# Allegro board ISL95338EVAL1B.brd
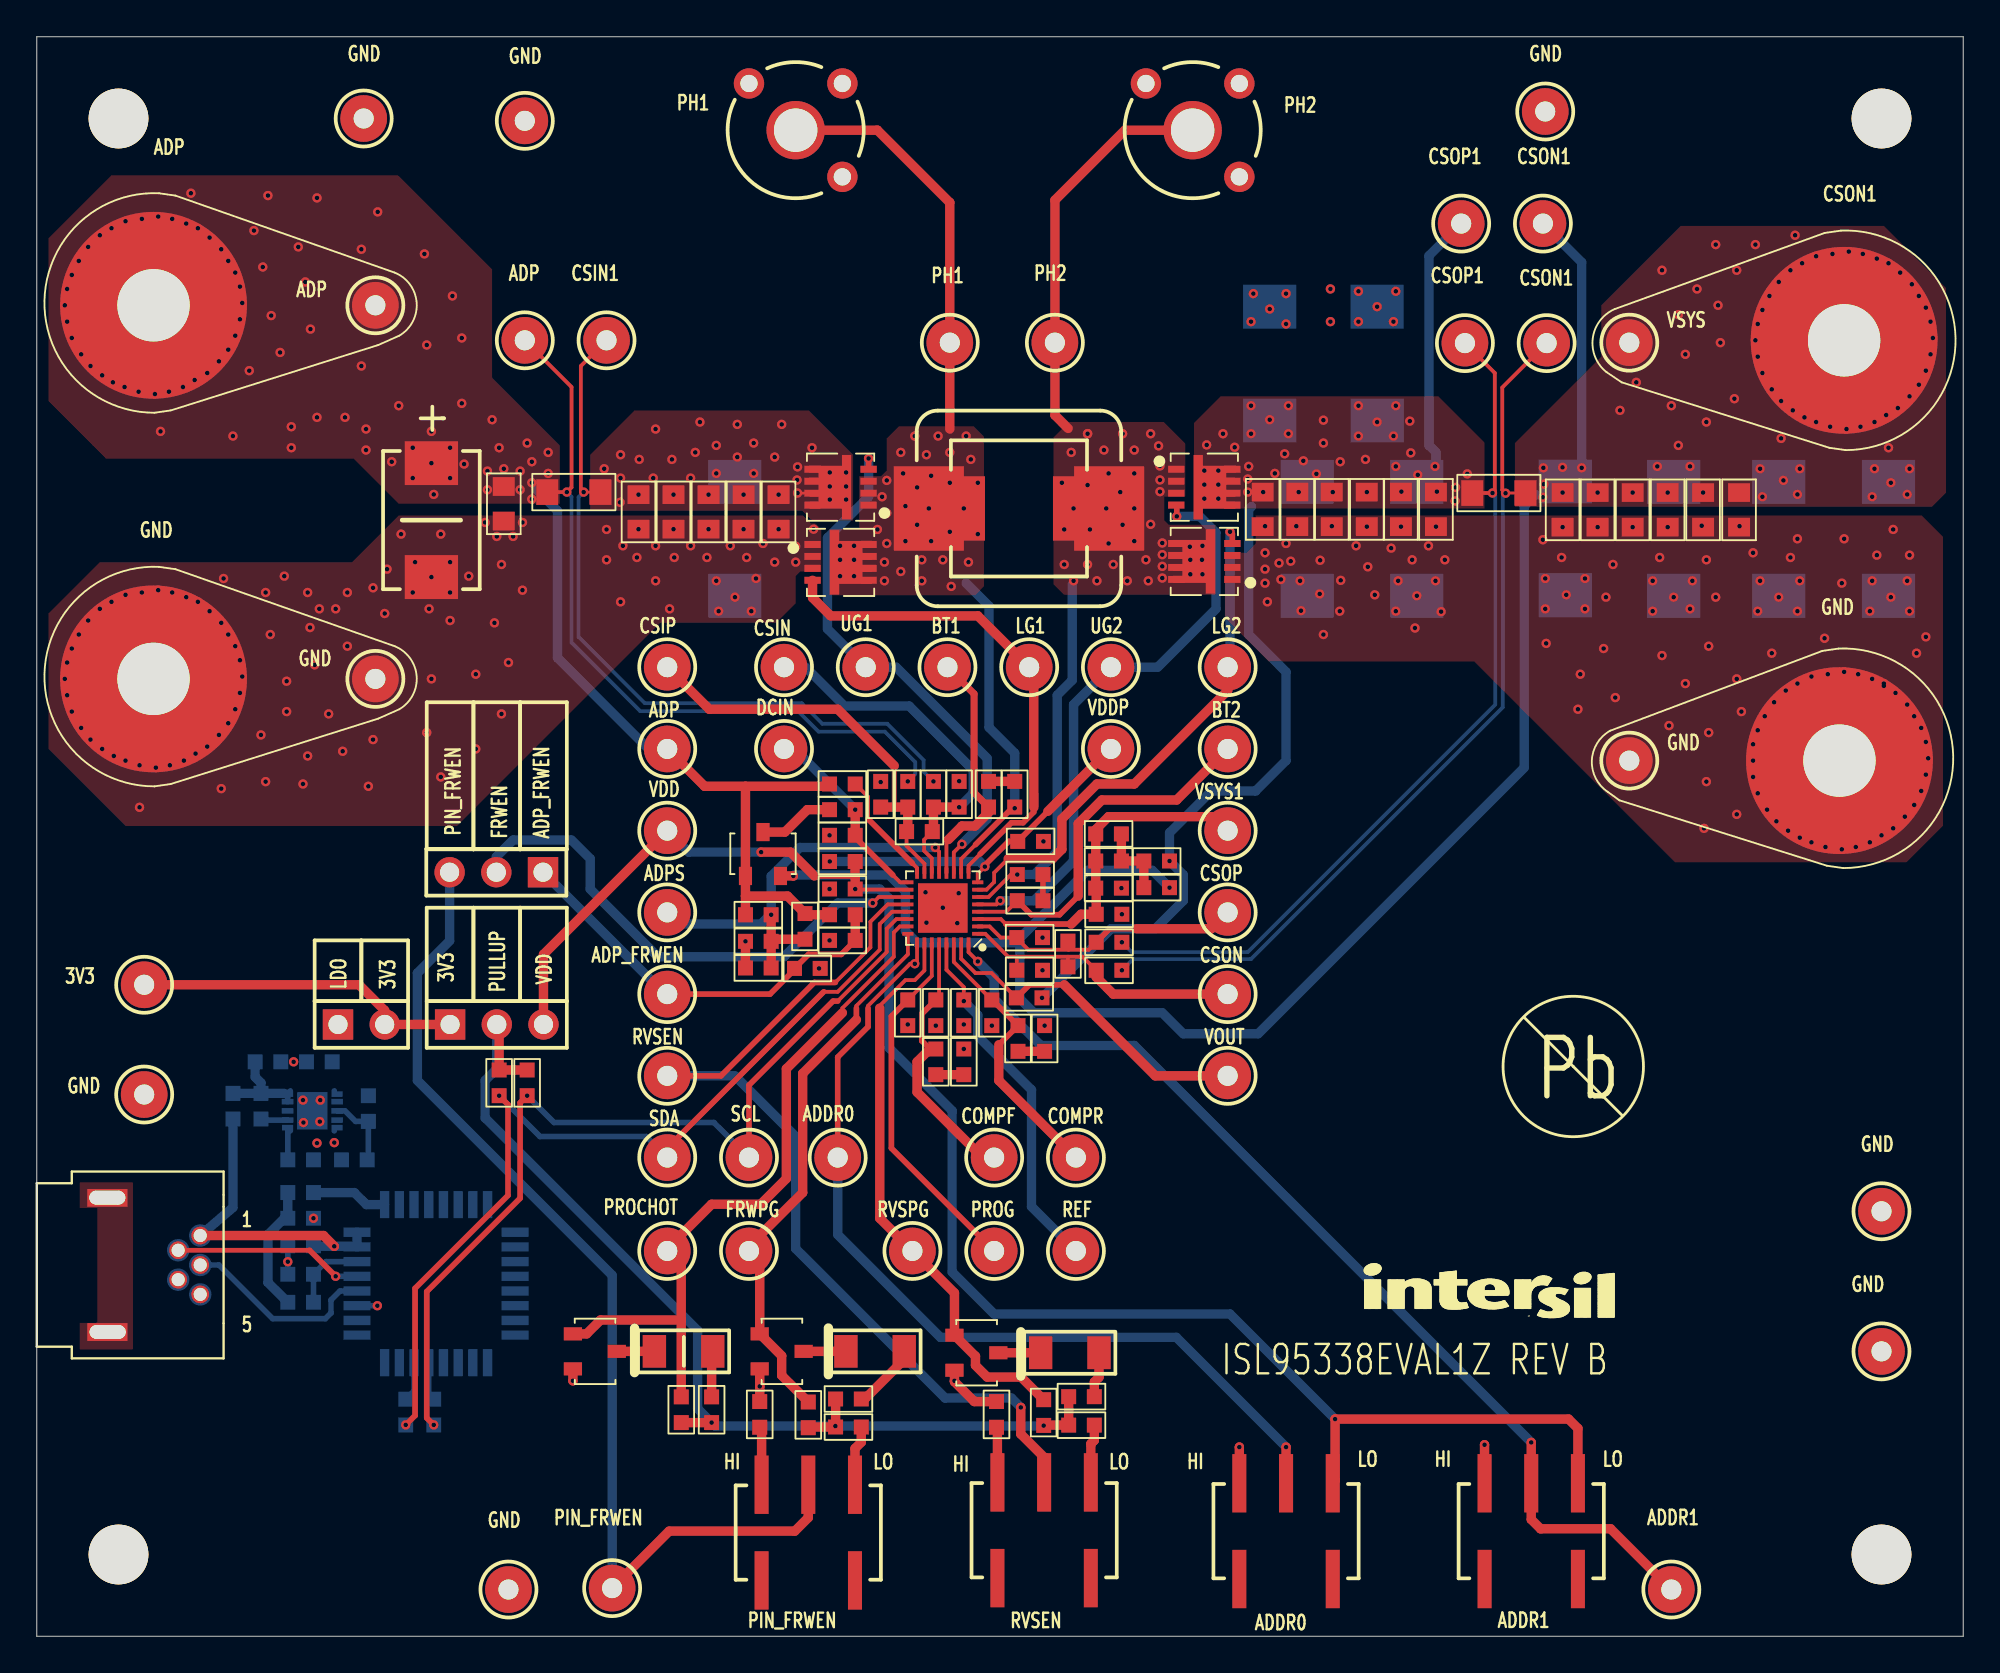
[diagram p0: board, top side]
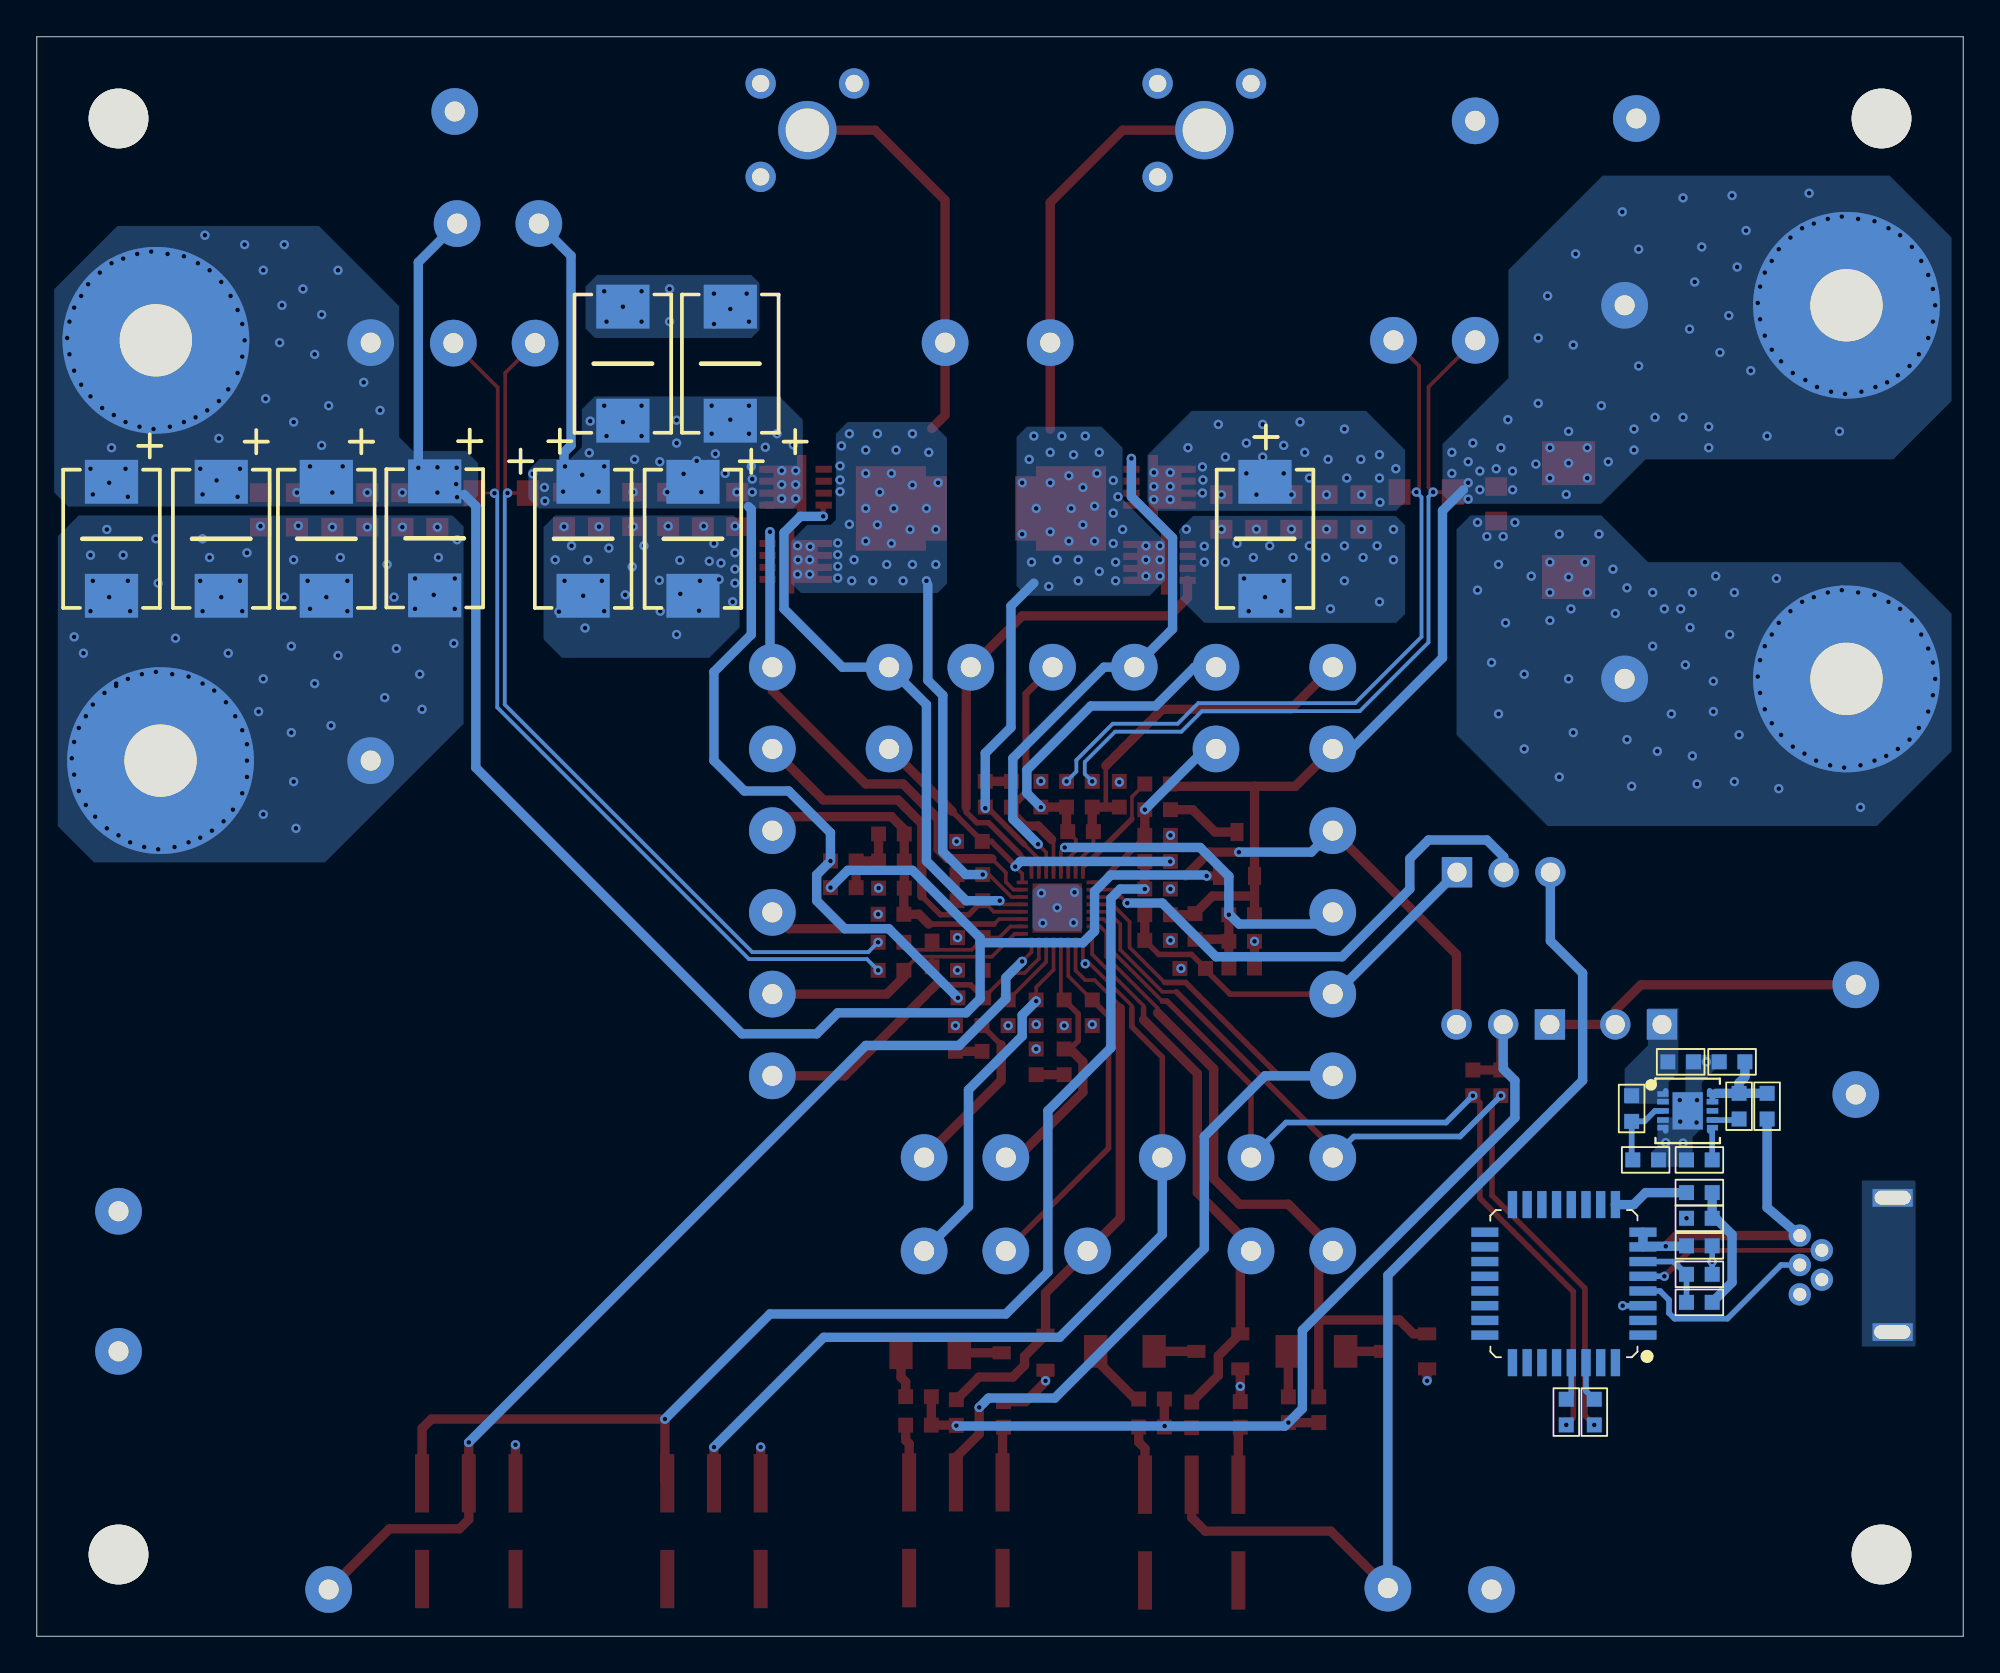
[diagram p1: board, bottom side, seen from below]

Outline 104.78 x 87 mm; copper layers: TOP, L2, L3, BOTTOM. Coordinates in mm from the lower left corner of the outline.
Outline path: 0,87 0,0 104.78,0 104.78,87 0,87 ; 3.18,23.5 arc(2.87,23.87) 3.21,24.21 4.47,24.21 arc(4.8,23.82) 4.39,23.5 3.18,23.5 ; 3.21,16.2 arc(2.9,16.56) 3.23,16.91 4.49,16.91 arc(4.82,16.51) 4.42,16.2 3.21,16.2

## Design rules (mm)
nets with their own width: min track width 0.152; nets CSON1 DCIN

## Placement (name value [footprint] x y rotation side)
C1  NC  [CAP_SANYO_D2]  100.71 59.69 270 bottom
C2  NC  [CAP_SANYO_D2]  94.74 59.69 270 bottom
C3  NC  [CAP_SANYO_D2]  89.03 59.69 270 bottom
C4  NC  [CAP_SANYO_D2]  83.13 59.72 270 bottom
C5  NC  [SM0805_DELTA]  90.63 61.26 90 top
C6  NC  [SM0805_DELTA]  92.58 61.26 90 top
C7  NC  [SM0805_DELTA]  82.99 61.26 90 top
C8  NC  [SM0805_DELTA]  84.89 61.26 90 top
C9  NC  [SM0805_DELTA]  86.8 61.26 90 top
C10  NC  [SM0805_DELTA]  88.7 61.26 90 top
C18  NC  [SM0805_DELTA]  25.4 61.59 90 top
C19  47u  [CAP_SANYO_D2]  37.97 59.69 270 bottom
C20  22u  [SM0805_DELTA]  40.35 61.15 90 top
C21  22u  [SM0805_DELTA]  38.44 61.15 90 top
C22  22u  [SM0805_DELTA]  36.54 61.15 90 top
C23  22u  [SM0805_DELTA]  34.63 61.15 90 top
C24  22u  [SM0805_DELTA]  32.73 61.15 90 top
C26  4.7uF  [SM0603_DELTA]  48.01 43.76 180 top
C28  1u  [SM0603_DELTA]  45.9 45.8 270 top
C29  1u  [SM0603_DELTA]  50.16 45.8 270 top
C30  0.22uF  [SM0603_DELTA]  51.77 45.8 90 top
C31  1uF  [SM0603_DELTA]  43.81 43.56 0 top
C32  1uF  [SM0603_DELTA]  54.05 43.23 180 top
C33  1uF  [SM0603_DELTA]  43.81 40.64 0 top
C34  1u  [SM0603_DELTA]  54 38 180 top
C35  1u  [SM0603_DELTA]  54 36.22 180 top
C36  0.22uF  [SM0603_DELTA]  54.03 40.01 180 top
C37  4.7u  [SM0603_DELTA]  56.08 37.11 90 top
C38  NC  [SM0603_DELTA]  39.24 36.35 0 top
C45  1000pF  [SM0603_DELTA]  50.42 33.91 90 top
C46  22n  [SM0603_DELTA]  50.42 31.24 270 top
C81  1uF  [SM0603_DELTA]  12.57 31.24 180 bottom
C82  1000pF  [SM0603_DELTA]  14.35 25.91 180 bottom
C83  1uF  [SM0603_DELTA]  15.37 31.24 0 bottom
C84  0.1uF  [SM0603_DELTA]  14.35 19.68 0 bottom
C85  0.1uF  [SM0603_DELTA]  14.35 22.73 180 bottom
C86  0.1uF  [SM0603_DELTA]  14.35 21.23 0 bottom
C87  NC  [SM0603_DELTA]  48.89 33.91 90 top
C98  NC  [SM0603_DELTA]  51.94 33.91 90 top
C99  22n  [SM0603_DELTA]  54.81 32.51 270 top
C100  0.1uF  [SM0603_DELTA]  41.91 36.32 180 top
C101  NC  [CAP_SANYO_D2]  21.46 60.71 270 top
C102  NC  [SM0603_DELTA]  41.78 38.61 90 top
C103  NC  [SM0603_DELTA]  58.29 40.69 180 top
C104  NC  [SM0603_DELTA]  58.29 43.64 180 top
C105  22u  [SM0805_DELTA]  70.43 61.29 90 top
C106  22u  [SM0805_DELTA]  72.34 61.29 90 top
C107  22u  [SM0805_DELTA]  74.19 61.29 90 top
C108  22u  [SM0805_DELTA]  76.1 61.29 90 top
C109  22u  [SM0805_DELTA]  68.55 61.29 90 top
C110  22u  [SM0805_DELTA]  66.67 61.29 90 top
C111  47u  [CAP_SANYO_D2]  69.09 59.69 270 bottom
C112  47u  [CAP_SANYO_D2]  75.06 59.69 270 bottom
C113  47u  [CAP_SANYO_D2]  67.06 69.22 90 bottom
C114  47u  [CAP_SANYO_D2]  72.9 69.22 90 bottom
D1  BAT54C  [SOT23]  39.5 42.55 0 top
J1  Banana_J  [111-07XX-001]  6.35 72.39 180 top
J2  Banana_J  [111-07XX-001]  6.35 52.07 180 top
J3  Banana_J  [111-07XX-001]  98.3 70.48 0 top
J4  Banana_J  [111-07XX-001]  98.04 47.62 0 top
J10  USB_MOL54819_0511  [MOL54819_0511]  8.89 20.19 0 top
JP4  conn_2p  [CONN2]  16.38 33.27 0 top
JP6  Jumper_3p  [CONN-1X3]  22.48 33.27 90 top
JP7  Jumper_3p  [CONN-1X3]  27.53 41.55 270 top
L1  10x10  [ETQP4LXXXWFC]  53.42 61.34 180 top
L2  2uH  [IND_PIMB061H]  53.42 61.34 0 top
LED1  597_3311_402  [SM1206]  35.18 15.49 0 top
LED2  597_3311_402  [SM1206]  45.59 15.49 0 top
LED3  597_3311_402  [SM1206]  56.18 15.42 0 top
NOREF  -  [unnamed]  4.44 82.55 0 top
NOREF#2  -  [#2]  0 87 0 top
NOREF#3  -  [#2]  104.78 0 90 top
NOREF#4  -  [#2]  70.52 16.32 0 top
NOREF#5  -  [unnamed]  4.44 4.44 0 top
NOREF#6  -  [unnamed]  100.33 4.44 0 top
NOREF#7  -  [#2]  83.57 30.99 0 top
NOREF#8  -  [unnamed]  100.33 82.55 270 top
NOREF#9  -  [#2]  -88.27 -76.84 0 top
Q1  AON7410  [PWRPAK_SINGLE_1212_8]  43.72 62.5 180 top
Q2  AON7410  [PWRPAK_SINGLE_1212_8]  43.72 58.41 0 top
Q3  AON7410  [PWRPAK_SINGLE_1212_8]  63.5 58.46 180 top
Q4  AON7410  [PWRPAK_SINGLE_1212_8]  63.5 62.5 0 top
Q8  2N7002  [SOT23]  40.51 15.49 270 top
Q9  2N7002  [SOT23]  30.35 15.49 270 top
Q10  2N7002  [SOT23]  51.1 15.42 270 top
R1  1  [SM0603_DELTA]  47.37 45.8 270 top
R2  1  [SM0603_DELTA]  48.77 45.8 270 top
R4  0  [SM0603_DELTA]  43.81 46.35 0 top
R6  0  [SM0603_DELTA]  53.19 45.8 90 top
R7  1  [SM0603_DELTA]  43.81 44.96 180 top
R8  4.7  [SM0603_DELTA]  43.81 42.14 180 top
R9  0  [SM0603_DELTA]  39.24 39.24 180 top
R10  1  [SM0603_DELTA]  58.32 37.74 180 top
R11  0  [SM0603_DELTA]  54.03 41.43 0 top
R12  0  [SM0603_DELTA]  53.98 34.72 180 top
R13  NC  [SM0603_DELTA]  39.24 37.8 0 top
R14  1  [SM0603_DELTA]  58.32 36.22 180 top
R15  10K  [SM0603_DELTA]  25.15 30.1 90 top
R16  10K  [SM0603_DELTA]  26.67 30.1 90 top
R23  133K  [SM0603_DELTA]  47.37 33.91 270 top
R27  698  [SM0603_DELTA]  48.89 31.24 270 top
R28  100K  [SM0603_DELTA]  44.15 11.38 0 top
R31  100K  [SM0603_DELTA]  56.82 11.48 0 top
R32  220  [SM0603_DELTA]  36.7 12.32 270 top
R33  220  [SM0603_DELTA]  44.15 12.9 180 top
R34  220  [SM0603_DELTA]  56.82 13.03 180 top
R36  10K  [SM0603_DELTA]  41.96 12.04 90 top
R38  10K  [SM0603_DELTA]  35.05 12.32 90 top
R39  10K  [SM0603_DELTA]  54.76 12.17 90 top
R44  100K  [SM0603_DELTA]  39.32 12.06 90 top
R45  100K  [SM0603_DELTA]  52.2 12.06 90 top
R81  10k  [SM0603_DELTA]  12.19 28.83 270 bottom
R82  5.62K  [SM0603_DELTA]  18.03 28.7 90 bottom
R83  1K  [SM0603_DELTA]  17.27 25.91 0 bottom
R84  0  [SM0603_DELTA]  10.67 28.83 270 bottom
R85  0  [SM0603_DELTA]  20.07 12.19 90 bottom
R86  0  [SM0603_DELTA]  21.59 12.19 90 bottom
R87  1K  [SM0603_DELTA]  14.35 18.16 180 bottom
R88  1K  [SM0603_DELTA]  14.35 24.13 0 bottom
R93  0  [SM0603_DELTA]  58.29 42.16 180 top
R94  NC  [SM0603_DELTA]  58.32 39.27 0 top
R97  698  [SM0603_DELTA]  53.37 32.51 270 top
R98  402K  [SM0603_DELTA]  43.81 39.24 180 top
R99  135k  [SM0603_DELTA]  43.81 37.85 0 top
R102  NC  [SM0603_DELTA]  60.91 42.16 0 top
R103  0  [SM0603_DELTA]  60.91 40.72 180 top
RS1  0.02  [SM1206_DELTA]  29.21 62.23 180 top
RS2  0.01  [SM1206_DELTA]  79.52 62.18 180 top
SW1  GT11MSCKE  [GT11SC]  41.96 5.64 180 top
SW2  GT11MSCKE  [GT11SC]  54.79 5.77 180 top
SW3  GT11MSCKE  [GT11SC]  67.94 5.71 180 top
SW4  GT11MSCKE  [GT11SC]  81.28 5.71 180 top
TP1  KEYSTONE-PN-500X-100P40H  [MTP500X]  18.41 72.39 0 top
TP2  KEYSTONE-PN-500X-100P40H  [MTP500X]  18.41 52.07 0 top
TP3  KEYSTONE-PN-500X-100P40H  [MTP500X]  26.54 70.48 270 top
TP4  KEYSTONE-PN-500X-100P40H  [MTP500X]  86.61 70.36 0 top
TP5  KEYSTONE-PN-500X-100P40H  [MTP500X]  86.61 47.62 0 top
TP6  KEYSTONE-PN-500X-100P40H  [MTP500X]  30.99 70.48 270 top
TP7  KEYSTONE-PN-500X-100P40H  [MTP500X]  34.29 48.26 0 top
TP8  KEYSTONE-PN-500X-100P40H  [MTP500X]  81.91 76.83 0 top
TP9  KEYSTONE-PN-500X-100P40H  [MTP500X]  45.09 52.7 90 top
TP10  KEYSTONE-PN-500X-100P40H  [MTP500X]  58.42 52.7 0 top
TP11  KEYSTONE-PN-500X-100P40H  [MTP500X]  40.64 52.7 0 top
TP12  KEYSTONE-PN-500X-100P40H  [MTP500X]  34.29 52.7 90 top
TP13  Probe Socket  [TEK131-4353-00]  62.86 81.91 0 top
TP14  Probe Socket  [TEK131-4353-00]  41.27 81.91 0 top
TP15  KEYSTONE-PN-500X-100P40H  [MTP500X]  49.53 52.7 0 top
TP16  KEYSTONE-PN-500X-100P40H  [MTP500X]  53.98 52.7 0 top
TP17  KEYSTONE-PN-500X-100P40H  [MTP500X]  40.64 48.26 0 top
TP18  KEYSTONE-PN-500X-100P40H  [MTP500X]  64.77 52.7 0 top
TP19  KEYSTONE-PN-500X-100P40H  [MTP500X]  58.42 48.26 0 top
TP20  KEYSTONE-PN-500X-100P40H  [MTP500X]  34.29 43.81 0 top
TP21  KEYSTONE-PN-500X-100P40H  [MTP500X]  34.29 39.37 0 top
TP22  KEYSTONE-PN-500X-100P40H  [MTP500X]  64.77 48.26 0 top
TP23  KEYSTONE-PN-500X-100P40H  [MTP500X]  77.67 70.33 90 top
TP24  KEYSTONE-PN-500X-100P40H  [MTP500X]  34.29 26.04 0 top
TP25  KEYSTONE-PN-500X-100P40H  [MTP500X]  64.77 43.81 0 top
TP26  KEYSTONE-PN-500X-100P40H  [MTP500X]  38.73 26.04 0 top
TP27  KEYSTONE-PN-500X-100P40H  [MTP500X]  64.77 39.37 0 top
TP28  KEYSTONE-PN-500X-100P40H  [MTP500X]  34.29 34.92 0 top
TP29  KEYSTONE-PN-500X-100P40H  [MTP500X]  82.12 70.33 90 top
TP30  KEYSTONE-PN-500X-100P40H  [MTP500X]  64.77 34.92 0 top
TP31  KEYSTONE-PN-500X-100P40H  [MTP500X]  43.56 26.04 0 top
TP32  KEYSTONE-PN-500X-100P40H  [MTP500X]  88.9 2.54 0 top
TP33  KEYSTONE-PN-500X-100P40H  [MTP500X]  52.07 20.95 0 top
TP34  KEYSTONE-PN-500X-100P40H  [MTP500X]  56.52 26.04 0 top
TP35  KEYSTONE-PN-500X-100P40H  [MTP500X]  64.77 30.48 0 top
TP36  KEYSTONE-PN-500X-100P40H  [MTP500X]  56.52 20.95 0 top
TP37  KEYSTONE-PN-500X-100P40H  [MTP500X]  52.07 26.04 0 top
TP43  KEYSTONE-PN-500X-100P40H  [MTP500X]  31.29 2.62 0 top
TP44  KEYSTONE-PN-500X-100P40H  [MTP500X]  34.29 30.48 0 top
TP45  KEYSTONE-PN-500X-100P40H  [MTP500X]  38.73 20.95 0 top
TP46  KEYSTONE-PN-500X-100P40H  [MTP500X]  34.29 20.95 0 top
TP47  KEYSTONE-PN-500X-100P40H  [MTP500X]  47.62 20.95 0 top
TP48  KEYSTONE-PN-500X-100P40H  [MTP500X]  26.54 82.42 0 top
TP49  KEYSTONE-PN-500X-100P40H  [MTP500X]  17.78 82.55 0 top
TP50  KEYSTONE-PN-500X-100P40H  [MTP500X]  5.84 29.46 0 top
TP51  KEYSTONE-PN-500X-100P40H  [MTP500X]  100.33 15.49 0 top
TP52  KEYSTONE-PN-500X-100P40H  [MTP500X]  100.33 23.11 0 top
TP53  KEYSTONE-PN-500X-100P40H  [MTP500X]  5.84 35.43 0 top
TP54  KEYSTONE-PN-500X-100P40H  [MTP500X]  25.65 2.54 0 top
TP55  KEYSTONE-PN-500X-100P40H  [MTP500X]  82.04 82.93 0 top
TP56  KEYSTONE-PN-500X-100P40H  [MTP500X]  49.66 70.36 0 top
TP57  KEYSTONE-PN-500X-100P40H  [MTP500X]  55.37 70.36 0 top
TP58  KEYSTONE-PN-500X-100P40H  [MTP500X]  77.47 76.83 0 top
U1  ISL95338  [QFN32_157X157_157_EP]  49.28 39.6 180 top
U2  C8051F320  [LQFP32_275X275_315]  21.72 19.18 90 bottom
U3  ISL80101IRAJZ  [DFN10_118X118_197_EP]  14.99 28.58 180 bottom

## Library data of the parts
C1-C4 C19 C101 C111-C114 = SANYO-POSCAP-D2: User Part Number: CAP_SANYO_D2
C5-C10 C18 C20-C24 C105-C110 = 0603: User Part Number: SM0805_DELTA
C26 C28-C37 C45 C46 C81-C87 C98 C99 R32-R34 = 0603: User Part Number: SM0603_DELTA
C38 C100 C102-C104 R1 R2 R4 R6-R16 R23 R27 R28 R31 R36 R38 R39 R44 R45 R84-R86 R93 R94 R97-R99 R102 R103 = 0201: User Part Number: SM0603_DELTA
D1 = BAT54C/SOT: User Part Number: SOT23
J1-J4 = Banana_J: User Part Number: 111-07XX-001
J10 = USB_MOL54819_0511: User Part Number: MOL54819_0511
JP4 = conn_2p: User Part Number: CONN2
JP6 JP7 = Jumper_3p: User Part Number: CONN-1X3
L1 = PANASONIC-ETQP4L: User Part Number: ETQP4LXXXWFC
L2 = COILCRAFT-CHIP-IND-0805: User Part Number: IND_PIMB061H
LED1-LED3 = LN1461C: User Part Number: SM1206
Q1-Q4 = AON7410_0: User Part Number: Si7655DN
Q8-Q10 = 2N7002: User Part Number: SOT23
R81-R83 R87 R88 = 0402: User Part Number: SM0603_DELTA
RS1 RS2 = 0805: User Part Number: SM1206_DELTA
SW1-SW4 = G3T12AP_9: User Part Number: GT11SC
TP1-TP12 TP15-TP37 TP43-TP58 = KEYSTONE-PN-500X-100P40H: User Part Number: MTP500X
TP13 TP14 = Probe Socket_4P: User Part Number: TEK131-4353-00
U1 = ISL9237_5: User Part Number: QFN32_157x157_157_EP
U2 = ISL65006_1: User Part Number: LQFP32_275X275_315
U3 = ISL80101_DFN: User Part Number: U3

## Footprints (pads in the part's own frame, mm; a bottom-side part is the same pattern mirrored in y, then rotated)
111-07XX-001
  round 10.16 hole 3.937: 1(0,0)
CAP_SANYO_D2
  rect 2.388x2.896 smd: 1(-3.099,0) 2(3.099,0)
CONN2
  rect 1.651x1.651 hole 1.041: 1(0,0)
  round 1.651 hole 1.041: 2(2.54,0)
CONN-1X3
  rect 1.651x1.651 hole 1.041: 1(0,0)
  round 1.651 hole 1.041: 2(0,-2.54) 3(0,-5.08)
DFN10_118X118_197_EP
  custom 0.119x0.119 smd: 1(-1.346,1.001) 5(-1.346,-1.001) 6(1.346,-1.001) 10(1.346,1.001)
  rect 0.635x0.305 smd: 2(-1.346,0.5) 3(-1.346,0) 4(-1.346,-0.5) 7(1.346,-0.5) 8(1.346,0) 9(1.346,0.5)
  rect 1.651x2.032 smd: 11(0,0)
ETQP4LXXXWFC
  rect 3.81x4.597 smd: 1(-4.902,0) 2(4.902,0)
GT11SC
  rect 0.762x3.175 smd: 1(2.54,-2.603) 2(0,-2.603) 3(-2.54,-2.603) 4(2.54,2.603) 6(-2.54,2.603)
IND_PIMB061H
  rect 2.35x3.5 smd: 1(-3.025,0) 2(3.025,0)
LQFP32_275X275_315
  rect 0.508x1.473 smd: 1(-2.8,-4.3) 2(-2,-4.3) 3(-1.2,-4.3) 4(-0.4,-4.3) 5(0.4,-4.3) 6(1.2,-4.3) 7(2,-4.3) 8(2.8,-4.3) 17(2.8,4.3) 18(2,4.3) 19(1.2,4.3) 20(0.4,4.3) 21(-0.4,4.3) 22(-1.2,4.3) 23(-2,4.3) 24(-2.8,4.3)
  rect 1.473x0.508 smd: 9(4.3,-2.8) 10(4.3,-2) 11(4.3,-1.2) 12(4.3,-0.4) 13(4.3,0.4) 14(4.3,1.2) 15(4.3,2) 16(4.3,2.8) 25(-4.3,2.8) 26(-4.3,2) 27(-4.3,1.2) 28(-4.3,0.4) 29(-4.3,-0.4) 30(-4.3,-1.2) 31(-4.3,-2) 32(-4.3,-2.8)
MOL54819_0511
  round 0.965 hole 0.711: 1(0,1.6) 2(-1.2,0.8) 3(0,0) 4(-1.2,-0.8) 5(0,-1.6)
  rect 2.184x0.965 hole 1.93x0.711: 6(-5.05,-3.65) 7(-5.05,3.65)
MTP500X
  round 2.54 hole 1.092: 1(0,0)
PWRPAK_SINGLE_1212_8
  rect 0.889x0.381 smd: 1(-1.524,0.975) 2(-1.524,0.325) 3(-1.524,-0.325) 4(-1.524,-0.975) 5(1.524,-0.975) 6(1.524,-0.325) 7(1.524,0.325) 8(1.524,0.975)
QFN32_157X157_157_EP
  rect 0.61x0.203 smd: 1(-1.9,1.4) 2(-1.9,1) 3(-1.9,0.6) 4(-1.9,0.2) 5(-1.9,-0.2) 6(-1.9,-0.6) 7(-1.9,-1) 8(-1.9,-1.4) 17(1.9,-1.4) 18(1.9,-1) 19(1.9,-0.6) 20(1.9,-0.2) 21(1.9,0.2) 22(1.9,0.6) 23(1.9,1) 24(1.9,1.4)
  rect 0.203x0.61 smd: 9(-1.4,-1.9) 10(-1,-1.9) 11(-0.6,-1.9) 12(-0.2,-1.9) 13(0.2,-1.9) 14(0.6,-1.9) 15(1,-1.9) 16(1.4,-1.9) 25(1.4,1.9) 26(1,1.9) 27(0.6,1.9) 28(0.2,1.9) 29(-0.2,1.9) 30(-0.6,1.9) 31(-1,1.9) 32(-1.4,1.9)
  rect 2.692x2.692 smd: 33(0,0)
SM0603_DELTA
  rect 0.813x0.813 smd: 1(-0.699,0) 2(0.699,0)
SM0805_DELTA
  rect 1.016x1.194 smd: 1(-0.94,0) 2(0.94,0)
SM1206
  rect 1.27x1.778 smd: 1(-1.587,0) 2(1.587,0)
SM1206_DELTA
  rect 1.194x1.397 smd: 1(-1.448,0) 2(1.448,0)
SOT23
  rect 0.711x0.991 smd: 1(-0.953,-1.194) 2(0.953,-1.194) 3(0,1.194)
TEK131-4353-00
  round 3.175 hole 2.362: 1(0,0)
  round 1.651 hole 0.94: 2(2.54,-2.54) 3(2.54,2.54) 4(-2.54,2.54)
unnamed
  round 3.251 hole 3.251 unplated: (0,0)

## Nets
3V3: JP4.2 JP6.1 TP53.1
GND: C1.2(N) C2.2(N) C3.2(N) C4.2(N) C5.1 C6.1 C7.1 C8.1 C9.1 C10.1 C18.1 C19.2(N) C20.1 C21.1 C22.1 C23.1 C24.1 C28.1 C29.1 C31.1 C32.1 C33.1 C34.1 C35.1 C38.1 C45.1 C46.1 C81.1 C82.1 C83.1 C84.1 C85.1 C86.1 C87.1 C98.1 C99.1 C100.1 C101.2(N) C103.1 C105.1 C106.1 C107.1 C108.1 C109.1 C110.1 C111.2(N) C112.2(N) C113.2(N) C114.2(N) J2.1 J4.1 J10.4 J10.5 J10.6 J10.7 Q2.1(S#1) Q2.2(S#2) Q2.3(S#3) Q3.1(S#1) Q3.2(S#2) Q3.3(S#3) Q8.2(SOURCE) Q9.2(SOURCE) Q10.2(SOURCE) R13.1 R23.2 R44.2 R45.2 R83.1 R94.2 R99.1 SW3.1 SW4.1 TP2.1 TP5.1 TP13.2(GND2) TP13.3(GND3) TP13.4(GND4) TP14.2(GND2) TP14.3(GND3) TP14.4(GND4) TP48.1 TP49.1 TP50.1 TP51.1 TP52.1 TP54.1 TP55.1 U1.33(PGND) U2.3(GND) U3.4(PG) U3.5(GND) U3.11(EP)
VDD: C33.2 JP6.3 R8.1 SW3.3 SW4.3 TP20.1 U1.18(VDD)
VDDP: C32.2 R8.2 TP19.1 U1.8(VDDP)
ADDR0: SW3.2 TP31.1 U1.25(ADDR0)
ADDR1: SW4.2 TP32.1 U1.32(ADDR1)
ADP: C18.2 C101.1(P) C102.2 D1.1(C1) J1.1 R1.1 R4.1 R9.2 R98.2 RS1.2 TP1.1 TP3.1 TP7.1
ADP_FRWEN: C100.2 JP7.1 R98.1 R99.2 TP28.1
ADPS: C38.2 C102.1 R9.1 R13.2 TP21.1 U1.13(ADPS)
BT1: C30.1 TP15.1 U1.12(BOOT1)
BT2: C36.2 TP22.1 U1.4(BOOT2)
COMPF: C87.2 R27.1 TP37.1 U1.28(COMPF)
COMPR: C98.2 R97.1 TP34.1 U1.30(COMPR)
CSIN: C26.1 C29.2 R2.2 TP11.1 U1.14(CSIN)
CSIN1: C19.1(P) C20.2 C21.2 C22.2 C23.2 C24.2 Q1.5(D#5) Q1.6(D#6) Q1.7(D#7) Q1.8(D#8) R2.1 RS1.1 TP6.1
CSIP: C26.2 C28.2 R1.2 TP12.1 U1.15(CSIP)
CSON: C35.2 C37.1 R14.2 TP30.1 U1.1(CSON)
CSON1: C1.1(P) C2.1(P) C3.1(P) C4.1(P) C5.2 C6.2 C7.2 C8.2 C9.2 C10.2 D1.2(C2) J3.1 R14.1 R103.1 RS2.1 TP4.1 TP8.1 TP29.1
CSOP: C34.2 C37.2 R10.2 TP27.1 U1.2(CSOP)
CSOP1: C105.2 C106.2 C107.2 C108.2 C109.2 C110.2 C111.1(P) C112.1(P) C113.1(P) C114.1(P) Q4.5(D#5) Q4.6(D#6) Q4.7(D#7) Q4.8(D#8) R10.1 R12.1 R102.2 RS2.2 TP23.1 TP58.1
DCIN: C31.2 R7.1 TP17.1 U1.17(DCIN)
FRWEN: JP7.2 U1.19(FRWEN)
FRWPG: Q8.1(GATE) R36.2 TP45.1 U1.24(FRWPG)
LG1: Q2.4(G) TP16.1 U1.9(LGATE1)
LG2: Q3.4(G) TP18.1 U1.7(LGATE2)
P1.4: U2.22(P1.4)
P1.5: U2.21(P1.5)
P1.6: U2.20(P1.6)
P1.7: U2.19(P1.7)
P2.0: U2.18(P2.0)
P2.1: U2.17(P2.1)
P2.2: U2.16(P2.2)
P2.3: U2.15(P2.3)
P2.4: U2.14(P2.4)
P2.5: U2.13(P2.5)
P2.6: U2.12(P2.6)
P2.7: U2.11(P2.7)
P3.0/C2D: U2.10(P3.0/C2D)
PH1: L1.2 L2.1 Q1.1(S#1) Q1.2(S#2) Q1.3(S#3) Q2.5(D#5) Q2.6(D#6) Q2.7(D#7) Q2.8(D#8) R6.1 TP14.1(SIGNAL) TP56.1 U1.10(PHASE1)
PH2: L1.1 L2.2 Q3.5(D#5) Q3.6(D#6) Q3.7(D#7) Q3.8(D#8) Q4.1(S#1) Q4.2(S#2) Q4.3(S#3) R11.1 TP13.1(SIGNAL) TP57.1 U1.6(PHASE2)
PIN_FRWEN: JP7.3 SW1.2 TP43.1
PROCHOT: Q9.1(GATE) R38.2 TP46.1 U1.23(PROCHOT)
PROG: R23.1 TP33.1 U1.27(PROG)
PULLUP: JP6.2 R15.2 R16.2 R28.1 R31.1 R32.2 R33.2 R34.2 R36.1 R38.1 R39.1
REF: C45.2 TP36.1 U1.29(REF)
RVSEN: SW2.2 TP44.1 U1.20(RVSEN)
RVSPG: Q10.1(GATE) R39.2 TP47.1 U1.26(RVSPG)
SCL: R16.1 R86.1 TP26.1 U1.22(SCL)
SDA: R15.1 R85.1 TP24.1 U1.21(SDA)
UG1: Q1.4(G) TP9.1 U1.11(UGATE1)
UG2: Q4.4(G) TP10.1 U1.5(UGATE2)
VOUT: R12.2 TP35.1 U1.31(VOUT)
VSYS1: C103.2 C104.2 R93.2 R94.1 TP25.1 U1.3(VOUTS)
N3388611: C85.2 R87.2 R88.1
N3403853: R86.2 U2.29(P0.5)
N3403912: R85.2 U2.30(P0.4)
N3404418: C86.2 J10.1 R84.2 U2.7(REGIN) U2.8(VBUS)
N3404574: J10.2 U2.5(D-)
N3404616: J10.3 U2.4(D+)
N3405190: C84.2 R87.1 U2.6(VDD)
N3405391: R88.2 U2.9(RST/C2CK)
N3864784: R81.2 U3.7(ENABLE)
N3864951: C82.2 U3.6(SS)
N3865034: C83.2 JP4.1 R82.2 U3.1(VOUT#1) U3.2(VOUT#2)
N3865052: R82.1 R83.2 U3.3(SENSE/ADJ)
N3866091: C81.2 R81.1 R84.1 U3.9(VIN#9) U3.10(VIN#10)
N3880625: C46.2 R27.2
N3892442: R4.2 U1.16(ADP)
N3896496: D1.3(A) R7.2
N3899462: LED3.2(ANODE) R34.1
N3906567: R44.1 SW1.1
N3906607: R28.2 SW1.3
N3907387: R45.1 SW2.1
N3907453: R31.2 SW2.3
N3914358: LED2.2(ANODE) R33.1
N3914362: LED2.1(CATHODE) Q8.3(DRAIN)
N3952115: C36.1 R11.2
N4021953: C30.2 R6.2
N4039122: LED3.1(CATHODE) Q10.3(DRAIN)
N4143346: C104.1 R93.1 R102.1 R103.2
N4149486: C99.2 R97.2
N4161658: LED1.2(ANODE) R32.1
N4161662: LED1.1(CATHODE) Q9.3(DRAIN)

Pads without a net: SW1 4 6; SW2 4 6; SW3 4 6; SW4 4 6; U2 1 2 23 24 25 26 27 28 31 32; U3 8

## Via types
v1: diameter 0.508, hole 0.254, TOP to BOTTOM, 660 vias

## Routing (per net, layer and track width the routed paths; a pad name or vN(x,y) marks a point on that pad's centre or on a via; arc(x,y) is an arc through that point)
3V3: length 18
  TOP w0.508: TP53.1 17.53,35.43 18.92,34.04 JP4.2 JP6.1
GND: length 13.9
  TOP w0.508: C38.1 v1(38.54,37.8) ; Q9.2 v1(29.16,13.89) ; Q10.2 v1(49.91,13.89) 49.91,13.84 50.99,12.76 R45.2 ; SW3.1 v1(65.41,10.29) ; SW4.1 v1(78.74,10.41) ; Q8.2 v1(39.32,13.59) R44.2
  BOTTOM w0.305: U2.3 v1(18.52,17.98) ; C84.1 v1(13.65,20.37) C86.1
  vias: v1(1.52,52.07) v1(1.65,52.96) v1(1.65,51.18) v1(1.91,53.72) v1(1.91,50.29) v1(2.29,54.48) v1(2.41,49.4) v1(2.79,55.24) v1(2.92,48.77) v1(3.43,55.88) v1(3.56,48.26) v1(4.06,56.26) v1(4.19,47.88) v1(4.83,56.64) v1(4.83,47.62) v1(5.59,47.37) v1(5.59,45.09) v1(5.71,56.77) v1(6.48,47.24) v1(6.6,56.9) v1(7.24,47.37) v1(7.37,56.77) v1(8,47.62) v1(8.13,56.52) v1(8.64,48.01) v1(8.76,56.26) v1(9.27,48.39) v1(9.4,55.75) v1(9.91,49.02) v1(10.03,55.12) v1(10.03,46.1) v1(10.16,57.53) v1(10.41,54.48) v1(10.41,49.66) v1(10.79,53.85) v1(10.79,50.42) v1(11.05,53.09) v1(11.05,51.31) v1(11.18,52.2) v1(12.19,49.02) v1(12.45,56.77) v1(12.45,46.48) v1(12.7,54.48) v1(13.46,57.66) v1(13.59,51.94) v1(13.59,50.29) v1(13.97,31.24) v1(14.48,46.35) v1(14.48,29.16) v1(14.5,27.94) v1(14.73,56.77) v1(14.73,47.88) v1(14.86,54.86) v1(15.11,52.83) v1(15.05,22.73) v1(15.24,26.82) v1(15.37,55.88) v1(15.42,29.16) v1(15.39,27.99) v1(15.88,50.16) v1(16.18,26.85) v1(16.26,55.88) v1(16.64,48.13) v1(16.89,56.77) v1(16.89,53.85) v1(18.03,46.23) v1(18.29,57.02) v1(18.29,48.77) v1(18.92,55.63) v1(19.05,58.04) v1(19.81,59.94) v1(20.45,56.77) v1(20.57,58.42) v1(21.21,49.15) v1(21.34,55.88) v1(21.46,57.61) v1(21.46,52.07) v1(21.97,59.94) v1(21.97,46.74) v1(22.48,58.42) v1(22.48,56.77) v1(22.48,55.24) v1(23.49,57.66) v1(23.88,52.32) v1(23.88,48.26) v1(24.38,60.58) v1(24.89,55.12) v1(25.02,59.82) v1(25.27,58.29) v1(25.27,50.16) v1(25.65,52.96) v1(25.91,59.82) v1(26.42,60.58) v1(26.42,56.9) v1(30.99,60.2) v1(30.99,58.55) v1(31.75,56.26) v1(31.88,59.31) v1(32.64,58.67) v1(32.73,60.21) v1(33.66,59.31) v1(33.66,57.4) v1(34.42,55.88) v1(34.63,60.21) v1(34.67,58.67) v1(35.56,59.31) v1(36.54,60.21) v1(36.45,58.67) v1(36.96,57.4) v1(37.08,55.75) v1(37.72,59.31) v1(37.97,56.52) v1(38.44,60.21) v1(38.61,58.67) v1(38.86,55.75) v1(39.12,57.53) v1(39.5,59.44) v1(40.13,58.42) v1(40.35,60.21) v1(41.27,59.28) v1(41.27,58.42) v1(42.25,60.21) v1(42.55,36.32) v1(43.12,43.56) v1(43.12,40.64) v1(43.12,37.85) v1(45.9,46.46) v1(47.37,33.27) v1(48.34,40.46) v1(48.39,38.81) v1(48.89,33.21) v1(49.28,39.62) v1(50.14,40.41) v1(50.06,38.79) v1(50.16,46.51) v1(50.42,33.27) v1(50.42,31.94) v1(51.94,33.21) v1(54.7,38) v1(54.7,36.22) v1(54.75,43.23) v1(54.81,33.21) v1(58.99,40.69) v1(59.02,39.27) v1(66.04,71.5) v1(66.17,73.03) v1(66.8,60.38) v1(66.8,58.93) v1(66.8,58.04) v1(66.8,57.28) v1(66.93,56.26) v1(67.06,72.19) v1(67.56,58.37) v1(67.67,57.48) v1(67.94,73.03) v1(67.94,71.37) v1(67.94,59.44) v1(68.2,58.47) v1(68.5,60.38) v1(68.71,57.4) v1(68.76,55.78) v1(69.8,58.52) v1(69.77,56.69) v1(69.98,54.48) v1(70.36,73.28) v1(70.36,71.5) v1(70.43,60.38) v1(70.92,57.43) v1(70.87,55.75) v1(71.75,59.31) v1(71.88,73.15) v1(71.88,71.5) v1(72.34,60.35) v1(72.39,58.17) v1(72.77,56.64) v1(72.9,72.31) v1(73.66,59.18) v1(73.79,71.5) v1(73.91,73.15) v1(73.91,55.75) v1(74.04,57.4) v1(74.19,60.35) v1(74.8,58.55) v1(74.96,54.84) v1(75.06,56.59) v1(75.69,59.31) v1(76.1,60.35) v1(76.07,57.4) v1(76.38,55.73) v1(76.58,58.55) v1(81.91,59.64) v1(82.04,57.53) v1(82.04,55.88) v1(82.09,54) v1(82.93,58.67) v1(82.99,60.32) v1(83.19,56.64) v1(83.82,50.42) v1(83.95,52.32) v1(84.2,57.53) v1(84.2,55.88) v1(84.89,60.32) v1(85.22,53.72) v1(85.34,56.52) v1(85.72,58.29) v1(85.85,51.05) v1(86.8,60.32) v1(87.88,57.4) v1(87.88,55.75) v1(88.27,58.67) v1(88.39,53.34) v1(88.7,60.32) v1(88.77,49.53) v1(89.03,56.52) v1(89.66,51.82) v1(89.92,55.88) v1(90.04,57.4) v1(90.55,60.4) v1(90.68,43.94) v1(90.8,58.55) v1(90.8,46.48) v1(90.93,53.85) v1(90.93,49.15) v1(91.31,56.52) v1(92.46,52.07) v1(92.46,44.7) v1(92.61,60.38) v1(92.71,50.29) v1(93.34,58.93) v1(93.34,48.51) v1(93.34,47.62) v1(93.34,46.74) v1(93.6,55.75) v1(93.6,49.28) v1(93.6,45.85) v1(93.73,57.4) v1(93.98,50.04) v1(94.11,44.96) v1(94.36,53.47) v1(94.49,50.8) v1(94.61,44.32) v1(94.74,56.52) v1(95.12,51.43) v1(95.25,43.81) v1(95.38,58.67) v1(95.76,59.69) v1(95.76,55.75) v1(95.76,51.82) v1(95.89,57.4) v1(95.89,43.43) v1(96.52,52.2) v1(96.52,43.18) v1(97.23,54.28) v1(97.28,42.93) v1(97.41,52.32) v1(98.17,57.28) v1(98.17,42.8) v1(98.3,59.69) v1(98.3,52.45) v1(98.93,42.93) v1(99.06,52.32) v1(99.69,55.75) v1(99.69,43.18) v1(99.82,57.4) v1(99.82,52.07) v1(100.08,58.8) v1(100.33,43.56) v1(100.46,51.82) v1(100.46,51.69) v1(100.84,56.52) v1(100.97,60.2) v1(100.97,43.94) v1(101.09,51.31) v1(101.6,44.58) v1(101.73,57.4) v1(101.73,50.67) v1(101.85,58.8) v1(101.85,55.75) v1(102.11,50.04) v1(102.11,45.21) v1(102.23,53.47) v1(102.49,49.4) v1(102.49,45.97) v1(102.74,54.36) v1(102.74,48.64) v1(102.74,46.86) v1(102.87,47.75)
VDD: length 96.8
  TOP w0.203: U1.18 44.55,40.6 v1(44.51,40.64)
  TOP w0.305: 44.5,41.35 42.29,41.35
  TOP w0.508: v1(39.4,42.65) 41,42.65 42.29,41.35 ; v1(44.51,40.64) 44.51,41.34 44.5,41.35 44.5,42.03 R8.1 ; SW3.3 70.61,8.45 v1(70.61,11.81) 83.31,11.81 83.82,11.3 83.82,8.32 ; TP20.1 27.56,37.08 JP6.3
  BOTTOM w0.508: v1(44.51,40.64) 45.85,40.64 46.35,40.13 46.35,32 49.78,28.58 49.78,19.81 52.07,17.53 64.9,17.53 v1(70.61,11.81) ; TP20.1 35.46,42.65 v1(39.4,42.65)
VDDP: length 19.1
  TOP w0.203: U1.8 51.18,41.47 v1(51.56,41.86) 51.56,41.94
  TOP w0.305: 54.99,44.87 C32.2 52.86,43.23 51.56,41.94
  TOP w0.508: 54.99,44.87 58.38,48.26 TP19.1
  BOTTOM w0.508: v1(43.13,42.14) 51.28,42.14 v1(51.56,41.86)
ADDR0: length 48.9
  TOP w0.203: U1.25 47.88,36.7 v1(47.75,36.58) 47.5,36.58 45.21,34.29 45.21,34.16
  TOP w0.305: 45.21,34.16 45.21,33.15 43.56,31.5 TP31.1
  TOP w0.508: v1(67.94,10.29) SW3.2
  BOTTOM w0.508: v1(67.94,10.29) 61.98,16.26 49.15,16.26 43.56,21.84 TP31.1
ADDR1: length 56.2
  TOP w0.203: v1(51.18,36.7) 50.68,37.21 U1.32
  TOP w0.508: TP32.1 85.6,5.84 81.79,5.84 81.28,6.35 SW4.2 v1(81.28,10.54)
  BOTTOM w0.508: v1(81.28,10.54) 59.69,32.13 54.61,32.13 52.07,34.67 52.07,35.81 v1(51.18,36.7)
ADP: length 80.7
  TOP w0.203: TP3.1 29.08,67.95 29.08,62.48 v1(28.83,62.23) RS1.2
  TOP w0.508: R98.2 41.85,39.24 C102.2 40.83,40.26 38.54,40.26 ; R4.1 42.99,46.23 38.54,46.23 ; 38.54,46.23 36.32,46.23 TP7.1 ; 38.54,46.23 D1.1 38.54,40.26 ; 38.54,40.26 R9.2
  BOTTOM w0.203: v1(28.83,62.23) 29.08,61.98 29.08,54.05 32.82,50.32 41.4,50.32 42.52,49.2 46.13,49.2 47.78,47.55 47.78,46.9 v1(47.37,46.49)
  BOTTOM w0.508: TP7.1 33.27,48.26 28.32,53.21 28.32,61.21 27.18,62.36
  vias: v1(1.52,72.39) v1(1.65,73.28) v1(1.65,71.5) v1(1.91,74.04) v1(1.91,70.61) v1(2.29,74.8) v1(2.41,69.72) v1(2.79,75.56) v1(2.92,69.09) v1(3.43,76.2) v1(3.56,68.58) v1(4.06,76.58) v1(4.14,68.2) v1(4.83,76.96) v1(4.78,67.95) v1(5.54,67.69) v1(5.71,77.09) v1(6.43,67.56) v1(6.6,77.22) v1(6.73,65.53) v1(7.19,67.69) v1(7.37,77.09) v1(7.95,67.95) v1(8.13,76.83) v1(8.38,78.49) v1(8.59,68.33) v1(8.76,76.58) v1(9.27,68.71) v1(9.4,76.07) v1(9.91,69.34) v1(10.03,75.44) v1(10.41,74.8) v1(10.41,69.98) v1(10.67,65.28) v1(10.79,74.17) v1(10.79,70.74) v1(11.05,73.41) v1(11.05,71.63) v1(11.18,72.52) v1(11.56,68.83) v1(11.81,76.45) v1(12.29,74.47) v1(12.57,78.36) v1(12.75,71.83) v1(13.23,69.82) v1(13.84,65.79) v1(13.84,64.64) v1(14.22,75.56) v1(14.61,73.66) v1(14.88,71.09) v1(15.24,78.23) v1(15.24,66.29) v1(16.76,66.29) v1(17.65,75.44) v1(17.65,69.09) v1(17.91,65.66) v1(17.91,64.52) v1(18.54,77.47) v1(19.3,63.88) v1(19.68,66.93) v1(20.45,64.64) v1(20.45,62.99) v1(21.08,75.18) v1(21.21,70.23) v1(21.46,65.53) v1(21.46,63.8) v1(21.59,62.1) v1(22.48,64.64) v1(22.48,62.99) v1(22.61,72.9) v1(23.11,70.61) v1(23.11,67.06) v1(23.24,63.75) v1(24.51,63.37) v1(24.51,62.36) v1(24.77,66.17) v1(25.15,64.64) v1(25.4,63.5) v1(26.29,63.37) v1(26.29,62.36) v1(26.67,64.9) v1(26.92,63.88) v1(26.92,62.74) v1(26.92,61.85) v1(27.81,64.39) v1(27.81,63.25)
ADP_FRWEN: length 22.4
  TOP w0.305: TP28.1 39.88,34.92 41.21,36.26 C100.2 41.97,37.08 43.75,37.08 R99.2
  TOP w0.508: R98.1 R99.2
  BOTTOM w0.508: TP28.1 34.16,34.92 JP7.1
ADPS: length 24.1
  TOP w0.203: v1(48.87,42.9) 48.87,42.88 49.08,42.67 U1.13
  TOP w0.508: C102.1 40.06,37.91 R13.2 ; R13.2 C38.2 ; R13.2 v1(39.94,39.24)
  BOTTOM w0.508: TP21.1 34.92,38.73 39.38,38.73 39.94,39.29 ; 39.94,39.29 v1(39.94,39.24) ; 39.94,39.29 39.94,41.34 41.5,42.9 v1(48.87,42.9)
BT1: length 13.5
  TOP w0.203: 49.58,43.33 49.48,43.23 U1.12
  TOP w0.381: TP15.1 50.98,51.26 50.98,45.89 C30.1
  TOP w0.508: 49.58,43.33 50.32,44.07 51.03,44.07 51.77,44.81 C30.1
BT2: length 20.2
  TOP w0.203: U1.4 52.73,39.41 C36.2
  TOP w0.305: C36.2 54.09,39.24 55.63,39.24 56.64,40.26
  TOP w0.508: 56.64,40.26 56.64,44.2 57.93,45.48 61.99,45.48 TP22.1
COMPF: length 15
  TOP w0.203: U1.28 49.08,34.79 C87.2
  TOP w0.305: 48.58,31.94 48.13,32.39 48.13,33.85 C87.2 ; 48.86,31.94 R27.1
  TOP w0.508: TP37.1 51.44,26.04 47.88,29.59 47.88,31.24 48.58,31.94 48.86,31.94
COMPR: length 15.3
  TOP w0.203: C98.2 49.88,36.67 U1.30
  TOP w0.305: C98.2 51.97,34.61 R97.1 52.32,32.17
  TOP w0.508: TP34.1 52.32,30.23 52.32,32.17
CSIN: length 20.3
  TOP w0.203: C26.1 48.26,43.32 48.26,42.72 48.68,42.31 U1.14
  TOP w0.508: C26.1 48.77,43.83 R2.2 C29.2 v1(50.16,45.09)
  BOTTOM w0.508: v1(50.16,45.09) 50.93,45.85 50.93,47.12 47.45,50.6 43.92,50.6 41.81,52.7 TP11.1
CSIN1: length 41.5
  TOP w0.152: Q1.7 41.38,62.17 v1(41.38,62.18) ; RS1.1 v1(29.74,62.23)
  TOP w0.203: TP6.1 29.59,69.09 29.59,62.38 v1(29.74,62.23)
  BOTTOM w0.203: v1(29.74,62.23) 29.46,61.95 29.46,54.36 33.07,50.75 41.61,50.75 42.72,49.63 46.25,49.63 48.23,47.65 48.23,47.03 v1(48.77,46.49)
  vias: v1(30.86,63.5) v1(31.72,61.67) v1(31.75,64.26) v1(31.75,62.99) v1(32.73,62.09) v1(32.77,64.01) v1(33.53,62.99) v1(33.66,65.66) v1(34.54,64.01) v1(34.63,62.09) v1(35.56,62.99) v1(35.81,64.39) v1(36.07,66.04) v1(36.54,62.09) v1(36.96,64.77) v1(36.96,63.25) v1(38.1,65.91) v1(38.1,64.14) v1(38.44,62.09) v1(38.99,64.9) v1(38.99,63.25) v1(40.13,64.14) v1(40.35,62.09) v1(40.51,65.91) v1(41.38,63.6) v1(41.35,62.89) v1(42.16,64.64) v1(43.13,63.3) v1(43.13,62.53) v1(43.13,61.82) v1(44.02,63.3) v1(44.02,62.53) v1(44.02,61.82)
CSIP: length 22.3
  TOP w0.203: C26.2 47.31,42.99 48.28,42.02 U1.15
  TOP w0.254: 46.63,45.1 46.63,47.35
  TOP w0.508: 46.63,47.35 43.56,50.42 36.58,50.42 TP12.1 ; C26.2 47.37,43.83 R1.2 C28.2
CSON: length 16.5
  TOP w0.203: 56.08,36.96 C37.1 ; 56.08,36.96 56.88,36.96 R14.2 ; 56.08,36.96 53.3,36.96 ; 53.3,36.96 52.83,36.96 51.58,38.2 U1.1 ; 53.3,36.96 C35.2
  TOP w0.508: TP30.1 58.55,34.92 57.62,35.85 R14.2
CSON1: length 141.4
  TOP w0.152: v1(79.88,62.17) 79.89,62.18 RS2.1
  TOP w0.203: TP29.1 79.71,67.92 79.71,62.35 v1(79.88,62.17)
  TOP w0.508: D1.2 v1(41.15,41.35)
  BOTTOM w0.152: v1(81.91,61.95) 81.91,61.75
  BOTTOM w0.203: v1(59.02,36.22) 59.63,36.83 66.04,36.83 79.73,50.52 79.73,62.02 v1(79.88,62.17)
  BOTTOM w0.508: v1(41.15,41.35) 41.2,41.4 46.35,41.4 47.24,40.51 47.24,38.35 47.88,37.72 53.47,37.72 ; 81.53,62.1 80.9,61.47 80.9,47.24 66.42,32.77 62.36,32.77 61.21,33.91 54.23,33.91 53.47,34.67 53.47,37.72 ; v1(61.61,40.72) 60.67,41.66 57.15,41.66 53.47,37.97 53.47,37.72 ; TP8.1 84.02,74.73 84.02,63.7
  vias: v1(81.94,63.55) v1(81.97,62.66) v1(82.98,63.58) v1(82.99,62.2) v1(84.02,63.55) v1(84.89,62.2) v1(86.11,66.67) v1(86.8,62.2) v1(87,68.2) v1(88.14,63.63) v1(88.39,74.3) v1(88.7,62.2) v1(88.9,66.93) v1(89.28,71.88) v1(89.28,64.77) v1(89.66,69.72) v1(89.92,63.63) v1(90.3,73.28) v1(90.63,62.2) v1(90.8,66.04) v1(91.31,75.69) v1(91.44,72.39) v1(91.57,70.36) v1(92.33,67.31) v1(92.46,74.3) v1(93.47,75.69) v1(93.47,70.48) v1(93.6,71.37) v1(93.6,69.6) v1(93.73,63.5) v1(93.85,72.14) v1(93.85,68.71) v1(93.85,61.98) v1(94.23,72.9) v1(94.36,67.82) v1(94.74,73.66) v1(94.87,67.18) v1(94.87,65.15) v1(95,62.86) v1(95.38,74.3) v1(95.5,66.67) v1(95.63,76.2) v1(95.76,62.1) v1(95.89,63.5) v1(96.01,74.68) v1(96.14,66.29) v1(96.77,75.06) v1(96.77,66.04) v1(97.54,65.79) v1(97.66,75.18) v1(98.42,65.66) v1(98.55,75.31) v1(99.19,65.79) v1(99.31,75.18) v1(99.82,61.98) v1(99.95,66.04) v1(99.95,63.5) v1(100.08,74.93) v1(100.58,66.42) v1(100.71,74.68) v1(100.71,64.64) v1(100.84,62.74) v1(101.22,66.8) v1(101.35,74.17) v1(101.73,62.1) v1(101.85,67.44) v1(101.85,63.5) v1(101.98,73.53) v1(102.36,72.9) v1(102.36,68.07) v1(102.74,72.26) v1(102.74,68.83) v1(103,71.5) v1(103,69.72) v1(103.12,70.61)
CSOP: length 15.5
  TOP w0.203: C37.2 56.11,37.78 56.11,37.34 ; 56.11,37.34 57.21,37.34 R10.2 ; 56.11,37.34 53.92,37.34 53.3,37.96 C34.2 52.43,38 51.82,38.6 U1.2
  TOP w0.305: 59.82,38.48 58.36,38.48 R10.2
  TOP w0.508: TP27.1 63.88,38.48 59.82,38.48
CSOP1: length 98.9
  TOP w0.152: v1(65.86,62.23) C110.2
  TOP w0.203: RS2.2 v1(79.17,62.18) 79.3,62.31 79.3,68.71 TP23.1
  BOTTOM w0.203: v1(79.17,62.18) 79.32,62.03 79.32,50.67 65.86,37.21 59.55,37.21 v1(59.02,37.74)
  BOTTOM w0.508: 76.1,63.83 76.1,64.39 75.72,64.77 75.72,75.08 TP58.1 ; 66.07,61.44 65.91,61.29 65.91,54.48 67.94,52.45 67.94,47.62 66.29,45.97 63.88,45.97 61.61,43.7 v1(61.61,42.16) 62.36,41.41 62.36,40.01 60.83,38.48 58.43,38.48 v1(54.67,34.72)
  vias: v1(63.5,63.4) v1(63.5,62.64) v1(63.5,61.87) v1(63.63,64.8) v1(64.26,63.4) v1(64.26,62.64) v1(64.26,61.87) v1(64.52,65.41) v1(65.15,64.67) v1(65.91,63.63) v1(65.86,62.94) v1(66.04,66.93) v1(66.04,65.41) v1(66.7,62.23) v1(67.06,66.17) v1(67.34,63.25) v1(67.87,64.31) v1(68.07,66.93) v1(68.07,65.41) v1(68.63,62.23) v1(68.88,63.93) v1(69.6,63.22) v1(69.98,66.14) v1(69.98,64.9) v1(70.48,62.23) v1(70.89,63.88) v1(71.88,66.93) v1(71.88,65.28) v1(72.26,64.01) v1(72.34,62.23) v1(72.9,66.04) v1(73.79,65.28) v1(73.91,66.93) v1(73.91,63.63) v1(74.22,62.26) v1(74.68,66.09) v1(74.73,64.36) v1(75.11,63.17) v1(76.05,63.63) v1(76.15,62.26) v1(77.14,61.75) v1(77.17,62.48) v1(77.8,63.22)
DCIN: length 10.6
  TOP w0.203: 46.56,41.4 46.96,41 U1.17
  TOP w0.305: 44.51,43.45 46.56,41.4
  TOP w0.508: 44.51,43.45 C31.2 v1(44.51,44.96)
  BOTTOM w0.508: TP17.1 41.21,48.26 v1(44.51,44.96)
FRWEN: length 28.5
  TOP w0.203: v1(45.47,39.88) 45.79,40.2 U1.19
  BOTTOM w0.508: v1(45.47,39.88) 43.56,39.88 40.64,36.96 33.78,36.96 30.1,40.64 30.1,42.29 29.08,43.31 25.91,43.31 24.99,42.39 JP7.2
FRWPG: length 30.4
  TOP w0.203: 44.58,34.16 44.58,34.29 47.38,37.09 U1.24
  TOP w0.305: 44.58,33.53 44.58,34.16
  TOP w0.508: 44.58,33.53 41.66,30.61 41.66,24.13 38.73,21.21 TP45.1 39.32,20.37 Q8.1 40.51,15.25 40.51,14.19 R36.2
LG1: length 27.4
  TOP w0.203: 51.31,42.54 50.68,41.91 U1.9
  TOP w0.305: 51.31,42.54 53.01,44.25 53.64,44.25 54.22,44.82 54.22,45.08 54.23,45.09
  TOP w0.508: Q2.4 42.19,56.49 43.18,55.5 51.18,55.5 TP16.1 54.22,52.46 54.23,45.09
LG2: length 28.7
  TOP w0.203: U1.7 51.65,40.6 52.07,41.02 52.07,41.53 52.83,42.29
  TOP w0.305: v1(64.9,60.07) 65.02,59.94 Q3.4
  TOP w0.508: 52.83,42.29 55.24,42.29 55.75,42.8 55.75,44.45 57.66,46.35 59.69,46.35 64.77,51.43 TP18.1
  BOTTOM w0.508: TP18.1 64.9,52.83 v1(64.9,60.07)
PH1: length 40.5
  TOP w0.203: 51.05,43.05 50.27,42.27 U1.10
  TOP w0.305: v1(53.19,45.03) 53.04,45.03 51.05,43.05
  TOP w0.508: TP14.1 45.72,81.91 49.66,77.98 TP56.1 49.66,65.66
  BOTTOM w0.508: 50.55,57.28 51.79,56.03 51.79,49.43 53.19,48.03 v1(53.19,45.03)
  vias: v1(43.69,59.31) v1(43.69,58.55) v1(43.69,57.66) v1(44.45,59.31) v1(44.45,58.55) v1(44.45,57.66) v1(45.72,60.2) v1(45.97,61.98) v1(46.1,58.42) v1(46.1,57.4) v1(46.23,62.86) v1(46.23,61.09) v1(46.23,59.44) v1(46.99,64.39) v1(46.99,57.91) v1(47.12,63.25) v1(47.24,61.47) v1(47.24,59.56) v1(47.75,65.28) v1(47.88,62.48) v1(47.88,60.45) v1(48.13,58.55) v1(48.13,57.4) v1(48.39,64.26) v1(48.52,61.34) v1(48.64,63.12) v1(48.64,59.56) v1(49.02,65.28) v1(49.28,58.55) v1(49.66,64.39) v1(49.66,62.74) v1(49.66,60.07) v1(49.73,57.1) v1(50.42,61.34) v1(50.55,65.28) v1(50.67,58.42) v1(50.8,64.01) v1(51.18,62.74) v1(51.18,59.94)
PH2: length 42
  TOP w0.203: U1.6 51.76,40.2 52.98,41.43 v1(53.33,41.43)
  TOP w0.508: v1(57.15,65.41) 57.16,65.41 ; 55.38,70.35 55.38,78.11 59.18,81.91 TP13.1 ; 55.38,70.35 55.38,66.41 56.09,65.69 ; 55.38,70.35 TP57.1
  BOTTOM w0.508: v1(53.33,41.43) 54.25,41.43 55.5,42.67 55.5,51.18 56.31,51.99 56.31,57.2
  vias: v1(55.75,62.74) v1(55.88,60.2) v1(55.88,58.29) v1(56.26,64.39) v1(56.39,61.34) v1(56.39,57.4) v1(57.15,62.61) v1(57.15,58.29) v1(57.28,60.2) v1(57.66,57.4) v1(58.04,64.52) v1(58.17,61.34) v1(58.29,63.25) v1(58.29,59.44) v1(58.55,58.29) v1(58.93,62.23) v1(59.05,65.41) v1(59.05,60.45) v1(59.31,57.4) v1(59.69,64.52) v1(59.69,63.25) v1(59.69,61.34) v1(59.69,59.56) v1(60.32,58.55) v1(60.45,57.4) v1(60.58,65.41) v1(60.58,60.48) v1(61.01,64.74) v1(61.09,63.65) v1(61.09,62.89) v1(61.09,62.26) v1(61.21,59.46) v1(61.21,58.83) v1(61.21,58.19) v1(61.21,57.56) v1(62.71,59.26) v1(62.74,58.55) v1(62.74,57.76) v1(63.4,59.31) v1(63.37,58.55) v1(63.4,57.76)
PIN_FRWEN: length 58.1
  TOP w0.508: TP43.1 34.39,5.71 41.22,5.71 41.96,6.45 SW1.2
  BOTTOM w0.508: JP7.3 22.45,37.82 20.7,36.07 20.7,30.23 31.29,19.63 TP43.1
PROCHOT: length 39.3
  TOP w0.203: 43.81,33.91 43.81,34.16 46.61,36.96 46.61,38.27 46.94,38.6 U1.23
  TOP w0.508: Q9.1 29.91,16.45 30.66,17.2 35.05,17.2 ; 35.05,17.2 35.05,20.19 TP46.1 34.29,21.08 36.7,23.49 39.37,23.49 40.77,24.89 40.77,30.86 43.81,33.91 ; 35.05,17.2 R38.2
PROG: length 20
  TOP w0.203: U1.27 48.68,35.91 R23.1
  TOP w0.305: R23.1 46.48,33.72 46.48,26.54 TP33.1
PULLUP: length 56.8
  TOP w0.508: R36.1 42,11.38 R28.1 R33.2 ; v1(54.76,11.46) R39.1 54.78,11.48 R31.1 R34.2 ; R16.2 R15.2 25.15,33.15 JP6.2 ; v1(36.7,11.62) R38.1
  BOTTOM w0.508: JP6.2 25.02,30.86 24.38,30.23 24.38,28.19 35.94,16.64 35.94,12.38 v1(36.7,11.62) 36.89,11.43 v1(43.43,11.43) 54.74,11.43 v1(54.76,11.46)
REF: length 19.7
  TOP w0.203: v1(50.42,34.54) C45.2 50.42,35.31 49.48,36.25 U1.29
  BOTTOM w0.508: v1(50.42,34.54) 51.18,33.78 51.18,32.64 54.1,29.72 54.1,23.37 TP36.1
RVSEN: length 52.6
  TOP w0.203: 43.43,35.56 45.34,37.47 45.34,38.86 46.28,39.8 U1.20
  TOP w0.305: 43.43,35.56 42.29,35.56 37.21,30.48 TP44.1
  TOP w0.508: v1(53.52,12.45) 53.52,11 54.79,9.73 SW2.2
  BOTTOM w0.508: v1(53.52,12.45) 53.01,12.95 49.4,12.95 41.27,21.08 41.27,27.18 37.97,30.48 TP44.1
RVSPG: length 30.9
  TOP w0.203: 45.85,34.16 45.85,34.29 47.24,35.69 47.75,35.69 48.28,36.21 U1.26
  TOP w0.508: 45.85,34.16 45.85,22.73 TP47.1 49.91,18.67 Q10.1 51.05,15.23 51.05,14.73 51.69,14.1 53.53,14.1 R39.2
SCL: length 50.8
  TOP w0.203: 43.56,34.54 46.23,37.21 46.23,38.48 46.75,39.01 U1.22
  TOP w0.305: v1(21.59,11.49) 21.21,11.87 21.21,18.75 26.29,23.83 26.29,29.02 v1(26.67,29.4) ; 43.56,34.54 43.31,34.54 38.73,29.97 TP26.1
  BOTTOM w0.305: v1(26.67,29.4) 28.13,27.94 36.83,27.94 TP26.1
SDA: length 50.7
  TOP w0.203: 42.8,35.05 43.56,35.05 45.85,37.34 45.85,38.73 46.52,39.41 U1.21
  TOP w0.305: v1(20.07,11.49) 20.57,12 20.57,18.92 25.63,23.98 25.63,28.92 v1(25.15,29.4) ; TP24.1 34.29,26.54 42.8,35.05
  BOTTOM w0.305: v1(25.15,29.4) 27.37,27.18 33.15,27.18 TP24.1
UG1: length 29.4
  TOP w0.203: v1(50.32,43.08) 49.88,42.64 U1.11
  TOP w0.305: v1(45.24,64.06) Q1.4
  BOTTOM w0.508: v1(45.24,64.06) 45.24,61.98 43,59.74 43,54.79 TP9.1 46.74,52.7 51.69,47.75 51.69,44.45 v1(50.32,43.08)
UG2: length 31.9
  TOP w0.203: U1.5 52.2,39.8 v1(52.4,40.01)
  TOP w0.305: Q4.4 62,61.5 v1(62,60.91)
  BOTTOM w0.508: v1(62,60.91) 63.25,60.91 64.14,60.02 64.14,55.88 60.96,52.7 TP10.1 56.39,50.67 56.39,42.16 54.23,40.01 v1(52.4,40.01)
VOUT: length 18.6
  TOP w0.203: U1.31 50.28,36.85 51.05,36.07 51.93,36.07 R12.2
  TOP w0.305: R12.2 53.99,35.43 55.88,35.43
  TOP w0.508: 55.88,35.43 60.83,30.48 TP35.1
VSYS1: length 19.2
  TOP w0.203: 52.7,38.73 52.43,39.01 U1.3
  TOP w0.305: 56.26,38.73 52.7,38.73
  TOP w0.508: 56.26,38.73 56.79,39.27 R94.1 57.62,40.67 C103.2 R93.2 C104.2 57.59,43.88 58.29,44.58 64.01,44.58 TP25.1
N3388611: length 7
  BOTTOM w0.508: R87.2 12.57,19.24 12.57,21.84 13.46,22.73 C85.2 R88.1
N3403853: length 2.1
  BOTTOM w0.305: U2.29 21.32,13.16 R86.2
N3403912: length 2.2
  BOTTOM w0.305: R85.2 20.52,13.34 U2.30
N3404418: length 17.9
  TOP w0.508: v1(16.18,21.21) 15.6,21.79 J10.1
  BOTTOM w0.305: 17.39,21.21 U2.7
  BOTTOM w0.508: C86.2 15.07,21.21 v1(16.18,21.21) 17.39,21.21 ; J10.1 10.67,23.32 R84.2 ; U2.7 U2.8
N3404574: length 10.3
  TOP w0.254: J10.2 14.84,20.99
  TOP w0.305: 14.84,20.99 v1(16.26,19.58)
  BOTTOM w0.305: U2.5 v1(16.26,19.58)
N3404616: length 10.8
  BOTTOM w0.305: U2.4 16.49,18.78 16,18.29 16,17.58 15.7,17.27 12.83,17.27 9.91,20.19 J10.3
N3405190: length 4.2
  BOTTOM w0.305: U2.6 15.74,20.38 C84.2 R87.1
N3405391: length 4.1
  BOTTOM w0.508: U2.9 17.93,23.48 17.27,24.13 R88.2
N3864784: length 1.5
  BOTTOM w0.305: R81.2 12.25,28.07 U3.7
N3864951: length 1.7
  BOTTOM w0.305: U3.6 13.65,27.56 C82.2
N3865052: length 4.1
  BOTTOM w0.305: U3.3 16.76,28.58 17.34,28 R82.1 18.03,25.97 R83.2
N3866091: length 5.4
  BOTTOM w0.305: U3.10 13.64,29.34 ; 13.64,29.34 13.45,29.53 ; 13.64,29.34 U3.9
  BOTTOM w0.508: R81.1 13.45,29.53 ; R81.1 R84.1 ; R81.1 12.19,30.1 11.87,30.42 C81.2
N3880625: length 1.5
  TOP w0.508: R27.2 C46.2
N3892442: length 6.2
  TOP w0.203: U1.16 47.88,41.79 47.63,42.04 ; R4.2 45.21,45.66 45.21,44.45
  TOP w0.305: 45.21,44.45 47.63,42.04
N3896496: length 4.1
  TOP w0.508: R7.2 41.91,44.96 40.69,43.74 D1.3
N3899462: length 2.5
  TOP w0.508: LED3.2 57.77,14.08 57.52,13.83 R34.1
N3906567: length 3.2
  TOP w0.508: R44.1 39.42,11.26 SW1.1
N3906607: length 3.3
  TOP w0.508: R28.2 44.84,10.55 44.5,10.21 SW1.3
N3907387: length 3
  TOP w0.508: SW2.1 52.25,11.32 R45.1
N3907453: length 3.2
  TOP w0.508: SW2.3 57.33,10.46 57.52,10.66 R31.2
N3914358: length 3.7
  TOP w0.508: R33.1 45.03,12.9 47.18,15.05 LED2.2
N3914362: length 2.3
  TOP w0.508: LED2.1 Q8.3
N3952115: length 1.4
  TOP w0.305: R11.2 C36.1
N4021953: length 1.4
  TOP w0.508: C30.2 R6.2
N4039122: length 2.3
  TOP w0.508: LED3.1 Q10.3
N4143346: length 4.1
  TOP w0.508: R103.2 R102.1 R93.1 C104.1
N4149486: length 1.4
  TOP w0.508: R97.2 C99.2
N4161658: length 2.5
  TOP w0.508: R32.1 36.7,15.43 LED1.2
N4161662: length 2
  TOP w0.508: LED1.1 Q9.3

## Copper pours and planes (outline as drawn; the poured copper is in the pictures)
GND on TOP: 4.83,44.07 0.64,48.26 0.64,55.63 3.43,58.42 17.14,58.42 19.68,60.96 41.91,60.96 42.67,60.2 42.67,57.91 41.53,57.91 41.27,57.66 41.27,56.18 40.21,55.12 33.91,55.12 22.86,44.07
GND on TOP: 5.21,24.69 2.36,24.69 2.34,24.66 2.34,23.27 3.25,23.27 3.25,17.04 2.34,17.04 2.34,15.62 2.36,15.6 5.21,15.6 5.23,15.62 5.23,24.66
GND on TOP: 89.09,42.1 78.17,53.02 66.99,53.02 64.62,55.4 64.62,58.93 65.79,58.93 66.29,59.44 66.29,60.96 102.51,60.96 103.67,59.8 103.67,44.08 101.69,42.1
GND on BOTTOM: 65.47,71.06 65.91,70.61 74.42,70.61 74.93,71.12 74.93,73.41 74.3,74.04 65.91,74.04 65.47,73.6
GND on BOTTOM: 47.9,40.67 47.9,38.48 48.03,38.35 50.47,38.35 50.62,38.51 50.62,40.56 50.29,40.89 48.13,40.89
GND on BOTTOM: 101.65,42.09 103.63,44.07 103.63,59.82 102.49,60.96 82.17,60.96 81.56,60.35 81.56,49.63 89.1,42.09
GND on BOTTOM: 2.64,15.75 5.51,15.75 5.51,24.79 2.64,24.79 2.59,24.74 2.59,15.8
GND on BOTTOM: 30.86,60.93 41.88,60.93 42.65,60.17 42.65,56.49 41.27,55.12 30.84,55.12 30.35,55.6 30.35,60.43
GND on BOTTOM: 66.55,54.86 68.2,53.21 76.2,53.21 77.22,54.23 77.22,60.32 76.58,60.96 66.88,60.96 66.55,60.63
GND on BOTTOM: 12.95,31.62 12.95,30.86 13.46,30.86 14.22,30.1 14.22,27.58 14.27,27.58 14.72,27.14 14.72,25.54 14.71,25.53 16.97,25.53 16.97,26.31 16.64,26.64 16.64,28.22 15.72,28.22 15.72,29.46 15.11,29.46 15.11,31.62
GND on BOTTOM: 0.64,55.63 0.64,48.13 4.7,44.07 22.61,44.07 27.56,49.02 27.56,60.2 26.8,60.96 19.68,60.96 17.14,58.42 3.43,58.42
GND on L2: 8,0.99 8,8.64 0.64,8.64 0.64,80.64 7.11,80.64 7.11,86.36 97.16,86.36 97.16,80.04 103.89,80.04 103.89,8.89 97.28,8.89 97.28,0.99
GND on L3: 8,1.27 8,8.25 0.64,8.25 0.64,80.64 7.11,80.64 7.11,86.36 97.13,86.36 97.13,80.01 104.01,80.01 104.01,8.89 97.38,8.89 97.38,1.27
ADP on TOP: 3.77,64.05 0.64,67.18 0.64,76.03 4.06,79.46 19.63,79.46 24.77,74.33 24.77,68.45 28.45,64.77 28.45,61.59 19.68,61.59 17.23,64.05
ADP on BOTTOM: 3.81,64.01 0.64,67.18 0.64,76.07 4,79.44 19.61,79.44 24.74,74.31 24.74,68.43 28.32,64.85 28.32,62.08 27.84,61.59 19.68,61.59 17.27,64.01
CSIN1 on TOP (solid shape): 44.3,60.74 43.79,60.74 43.79,61.33 42.01,61.33 42.01,61.71 42.52,61.71 42.52,61.99 42.01,61.99 42.01,62.34 42.52,62.34 42.52,62.65 42.01,62.65 42.01,63 42.52,63 42.52,63.28 42.01,63.28 42.01,63.66 43.79,63.66 43.79,64.25 44.3,64.25
CSIN1 on TOP: 41.63,61.21 42.16,60.68 44.4,60.68 44.4,64.26 41.99,66.67 32.51,66.67 30.1,64.26 30.1,61.21
CSIN1 on BOTTOM: 44.37,61.72 44.37,64.24 41.96,66.65 32.49,66.65 30.35,64.52 30.35,61.7 30.84,61.21 43.87,61.21
CSON1 on TOP: 80.39,61.43 80.39,64.9 85.09,69.6 85.09,72.39 89.41,76.71 100.46,76.71 103.83,73.33 103.83,62.19 103.07,61.43
CSON1 on BOTTOM: 81.43,64.47 84.3,64.47 85.06,65.23 85.06,72.34 89.43,76.71 100.38,76.71 103.82,73.27 103.82,62.2 103.06,61.44 81.36,61.44 80.77,62.03 80.77,63.8
CSOP1 on TOP (solid shape): 63.42,63.67 65.2,63.67 65.2,63.28 64.69,63.28 64.69,63 65.2,63 65.2,62.65 64.69,62.65 64.69,62.34 65.2,62.34 65.2,61.99 64.69,61.99 64.69,61.71 65.2,61.71 65.2,61.33 63.42,61.33 63.42,60.74 62.92,60.74 62.92,64.25 63.42,64.25
CSOP1 on TOP: 62.94,61.34 62.94,65.99 64.39,67.44 76.23,67.44 78.74,64.92 78.74,61.34
CSOP1 on BOTTOM: 63.63,61.34 63.12,61.85 63.12,66.17 64.39,67.44 74.42,67.44 75.13,66.73 75.13,64.67 75.77,64.03 77.42,64.03 78.03,63.42 78.03,61.87 77.5,61.34
PH1 on TOP (solid shape): 43.64,59.58 45.42,59.58 45.42,59.19 44.91,59.19 44.91,58.92 45.42,58.92 45.42,58.56 44.91,58.56 44.91,58.25 45.42,58.25 45.42,57.9 44.91,57.9 44.91,57.62 45.42,57.62 45.42,57.24 43.64,57.24 43.64,56.65 43.13,56.65 43.13,60.16 43.64,60.16
PH1 on TOP: 43.1,56.62 43.1,60.22 44.73,60.22 44.73,63.09 45.92,63.09 46.23,63.4 46.23,65.15 46.89,65.81 50.95,65.81 51.51,65.25 51.51,57.1 51.03,56.62
PH1 on BOTTOM: 43.31,59.44 45.72,61.85 45.72,64.64 46.86,65.79 50.93,65.79 51.49,65.23 51.49,57.12 50.95,56.59 44.25,56.59 43.31,57.53
PH2 on TOP (solid shape): 64.08,56.71 63.58,56.71 63.58,57.29 61.8,57.29 61.8,57.67 62.31,57.67 62.31,57.95 61.8,57.95 61.8,58.31 62.31,58.31 62.31,58.61 61.8,58.61 61.8,58.97 62.31,58.97 62.31,59.25 61.8,59.25 61.8,59.63 63.58,59.63 63.58,60.21 64.08,60.21
PH2 on TOP: 55.88,56.64 55.3,57.23 55.3,65.2 56.13,66.04 61.29,66.04 62.46,64.87 62.46,61.98 61.32,61.98 61.32,60.71 61.57,60.45 64.11,60.45 64.11,56.64
PH2 on BOTTOM: 55.78,56.74 55.27,57.25 55.27,65.18 56.13,66.04 60.68,66.04 61.32,65.41 61.32,60.73 61.59,60.45 62.86,60.45 63.75,59.56 63.75,57.28 63.22,56.74
N3865034 on BOTTOM: 16.03,28.96 16.03,30.12 15.49,30.66 15.49,34.16 17.14,34.16 17.14,32.13 18.41,30.86 18.41,28.96

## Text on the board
BOTTOM: SolderSide - Bottom
TOP: Component Side - TOP
Ref Des/Silkscreen Top: 3V3 | GND | ADP | PIN_FRWEN | CSIN1 | ADP_FRWEN | PROCHOT | RVSEN | CSIP | ADPS | VDD | SDA | PH1 | HI | FRWPG | SCL | CSIN | DCIN | ADDR0 | UG1 | LO | RVSPG | BT1 | COMPF | PROG | LG1 | PH2 | COMPR | REF | VDDP | UG2 | VSYS1 | CSOP | CSON | VOUT | LG2 | BT2 | CSOP1 | ADDR1 | CSON1 | VSYS | LDO | PULLUP | FRWEN | ISL95338EVAL1Z REV B
L2: Internal Plane - L2
L3: Interbal etch - L3
DIMENSION: .028 | .076 | 3.  SMOBC SOLDERMASK BOTH SIDES USING RED RESIST. IAW IPC-SM-840 | 4.  SILKSCREEN BOTH SIDE(S) USING WHITE NON CONDUCTIVE EPOXY BASED | 1.  THIS IS A 4 LAYER BOARD WITH COMPONENTS ON BOTH SIDES. | 2.  PRINTED CIRCUIT BOARD SHALL BE 2 OUNCE COPPER. | INK. TRIM ALL SILKSCREEN 4mils FROM BARE COPPER | BOARD METERIAL TO BE EXPOXY BASED FR-4. | NOTES:
BODY_CENTER: SLOTS TO BE PLATED | DETAIL  A
DISPLAY_TOP: 13.6 Preprege | 13.6 Prepreg | 31 mil CORE | +/-10% | .062 | ADJUST CENTER CORE TO ACHIVE BOARD THICKNESS | 4 LAYER STACKING | LAYER 3 | LAYER 2 | LAYER 4 | LAYER 1 | SCALE: NONE | Top Etch 2 oz. Finished | PWR Plane 2 oz. | GND Plane 2 oz. | Bottom Etch 2 oz. Finished
DISPLAY_BOTTOM: MARGARET SAVIEO | 09-19-16 | ISL95338EVAL1ZB | Xunwei Yu | ISL95338EVAL1Z
PAGE_OUTLINE: NAME | ISL95338EVAL1Z | LAYER | DATE | REV. | 09/19/16 | B
User.9: Internal Etch - L4
User.10: PasteMask Top
User.11: PasteMask Bottom
User.12: SolderMask Top
User.13: SolderMask Bottom
User.14: Silkscreen Top
User.15: Silkscreen Bottom
User.16: NOTE: All VIAS to be TENTED. NO exposed copper pads on any | VIAS top or bottom Except VIAS in SMT pads. | 6 . ELECTROLESS NICKEL GOLD OR IMMERSION GOLD BOARD FINISH. | 7 . MINIMUM TRACE WIDTH 8 MILS/ SPACE 6 MILS | 5 . MANUFACTURE/FABRICATE TO MEET EU RoHS DIRECTIVE. | Tg > 170 C | ALL MATERIALS AND SOLDERMASK TO BE COMPLIANT TO EU RoHS | Td > 294 C | DIRECTIVE 20002/95/EC | LAMINATE AND RESIN MATERIAL PARAMETERS
User.18: Internal Etch - L5
User.20: Internal Etch - L6
User.21: Internal Plane - L7
User.22: Fabrication Drawing | N/A | 1 of 1 | B
User.23: Assembly Drawing | 1 of 1 | A
User.25: TOP ASSEMBLY
User.26: BOTTOM ASSEMBLY
User.29: FIGURE | SIZE | 10.0 | 28.0 | 37.0 | 41.0 | 43.0 | 93.0 | 155.0 | 128.0 | 76.0x28.0 | DRILL CHART: TOP to BOTTOM | ALL UNITS ARE IN MILS | PLATED | NON-PLATED | QTY | 660 | 5 | 6 | 8 | 51 | 2 | 4
User.32: U2 | R88 | C86 | R87 | C82 | C83 | U3 | R84 | R34 | C22 | R86 | R85 | C84 | R83 | R82 | C85 | R81 | C81
User.33: BOTTOM ASSEMBLY
